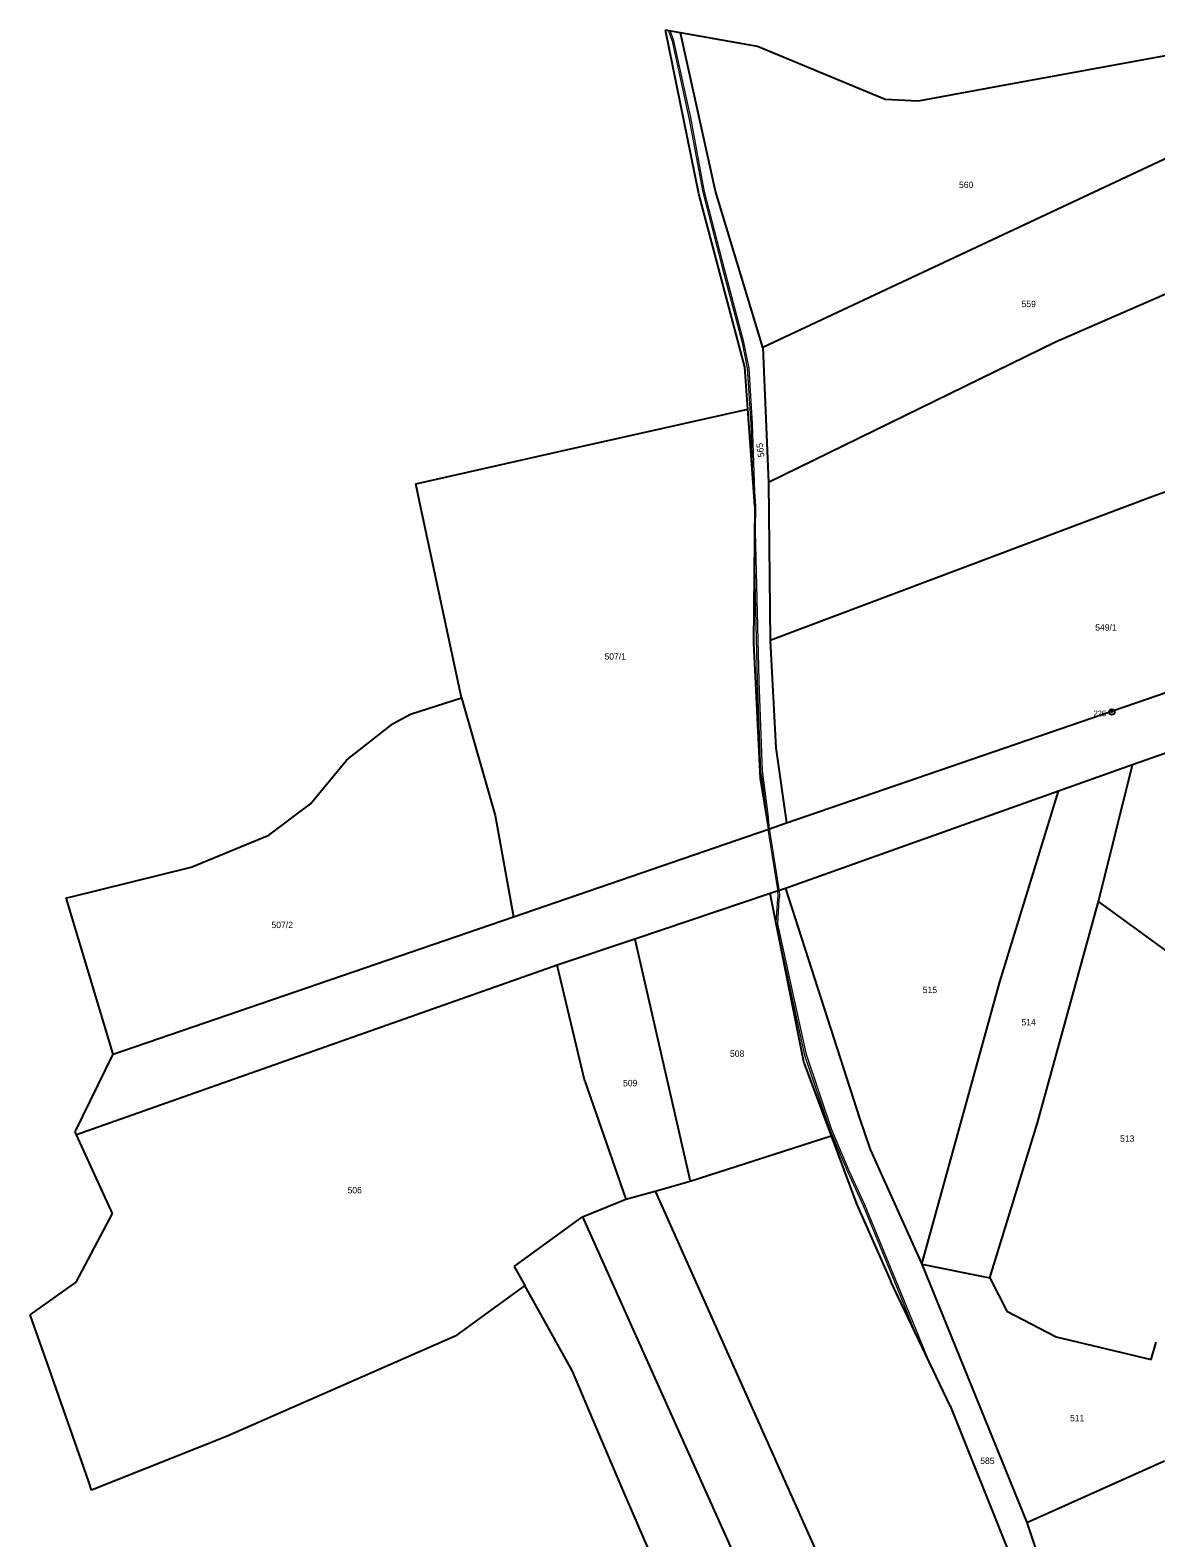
# Model space of a CAD drawing. Extents: x -664548 to -662415, y -1069720 to -1068208.
# Drawn here: x -664548.4 to -664249.9, y -1069341.5 to -1068942 of the extents above; entities that cross this region are included whole.
import ezdxf
from ezdxf.enums import TextEntityAlignment as Align

# ---------------------------------------------------------------- set-up
doc = ezdxf.new("R2010")
doc.units = 0
doc.header["$LTSCALE"] = 0.68
for name, color, linetype, lineweight in [('1', 7, 'Continuous', 25), ('13', 7, 'Continuous', 13), ('8', 7, 'Continuous', 25)]:
    doc.layers.add(name, color=color, linetype=linetype, lineweight=lineweight)
doc.layers.add('2', color=7, linetype='Continuous')

msp = doc.modelspace()

# ---------------------------------------------------------------- linework, layer by layer
at = {"layer": '1'}
for p, q in [((-664375.93, -1068942.69), (-664379.94, -1068941.98)), ((-664371.14, -1068985.33), (-664379.94, -1068941.98)), ((-664355.58, -1068946.3), (-664375.93, -1068942.69)), ((-664366.65, -1068984.69), (-664375.93, -1068942.69)), ((-664321.73, -1068960.32), (-664355.58, -1068946.3)), ((-664244.94, -1068948.35), (-664291.38, -1068956.85)), ((-664291.38, -1068956.85), (-664312.94, -1068960.8)), ((-664312.94, -1068960.8), (-664321.73, -1068960.32)), ((-664227.37, -1068966.62), (-664354.13, -1069026.11)), ((-664358.94, -1069031.29), (-664371.14, -1068985.33)), ((-664354.13, -1069026.11), (-664366.65, -1068984.69)), ((-664223.9, -1069001.69), (-664276.55, -1069024.67)), ((-664354.13, -1069026.11), (-664352.63, -1069061.84)), ((-664276.55, -1069024.67), (-664352.63, -1069061.84)), ((-664358.14, -1069042.38), (-664358.94, -1069031.29)), ((-664403.1, -1069052.48), (-664358.14, -1069042.38)), ((-664356.29, -1069068.06), (-664358.14, -1069042.38)), ((-664181.24, -1069041.54), (-664250, -1069065.31)), ((-664446.17, -1069062.16), (-664403.1, -1069052.48)), ((-664445.15, -1069066.92), (-664446.17, -1069062.16)), ((-664352.63, -1069061.84), (-664352.21, -1069103.72)), ((-664250, -1069065.31), (-664352.21, -1069103.72)), ((-664433.99, -1069118.89), (-664445.15, -1069066.92)), ((-664356.29, -1069068.06), (-664356.64, -1069104.38)), ((-664347.85, -1069152.04), (-664169.52, -1069090.79)), ((-664356.64, -1069104.38), (-664354.8, -1069140.28)), ((-664352.21, -1069103.72), (-664350.65, -1069132.16)), ((-664433.99, -1069118.89), (-664425.07, -1069150.06)), ((-664464.39, -1069135.33), (-664452.18, -1069125.7)), ((-664350.65, -1069132.16), (-664347.85, -1069152.04)), ((-664246.07, -1069133.11), (-664256.09, -1069136.68)), ((-664474.11, -1069147.02), (-664464.39, -1069135.33)), ((-664256.09, -1069136.68), (-664275.75, -1069143.67)), ((-664265.08, -1069172.85), (-664256.09, -1069136.68)), ((-664354.8, -1069140.28), (-664352.64, -1069153.69)), ((-664275.75, -1069143.67), (-664348.1, -1069169.43)), ((-664291.29, -1069194.2), (-664275.75, -1069143.67)), ((-664485.12, -1069155.29), (-664474.11, -1069147.02)), ((-664425.07, -1069150.06), (-664420.27, -1069176.92)), ((-664420.27, -1069176.92), (-664352.64, -1069153.69)), ((-664352.64, -1069153.69), (-664347.85, -1069152.04)), ((-664505.7, -1069163.78), (-664485.12, -1069155.29)), ((-664537.91, -1069171.7), (-664505.7, -1069163.78)), ((-664348.1, -1069169.43), (-664352.16, -1069170.79)), ((-664348.1, -1069169.43), (-664328.52, -1069230.33)), ((-664538.84, -1069171.93), (-664537.91, -1069171.7)), ((-664526.38, -1069213.36), (-664538.84, -1069171.93)), ((-664352.16, -1069170.79), (-664388.11, -1069182.84)), ((-664343.18, -1069215.8), (-664352.16, -1069170.79)), ((-664281.32, -1069231.52), (-664265.08, -1069172.85)), ((-664235.59, -1069194.44), (-664265.08, -1069172.85)), ((-664526.38, -1069213.36), (-664420.27, -1069176.92)), ((-664388.11, -1069182.84), (-664408.69, -1069189.74)), ((-664388.11, -1069182.84), (-664373.38, -1069247)), ((-664401.36, -1069220.5), (-664408.69, -1069189.74)), ((-664312, -1069269.03), (-664291.29, -1069194.2)), ((-664536.46, -1069233.88), (-664526.38, -1069213.36)), ((-664343.18, -1069215.8), (-664336.02, -1069234.94)), ((-664401.36, -1069220.5), (-664390.43, -1069251.77)), ((-664328.52, -1069230.33), (-664325.71, -1069238.59)), ((-664293.94, -1069272.63), (-664281.32, -1069231.52)), ((-664526.55, -1069255.58), (-664536.09, -1069234.68)), ((-664373.38, -1069247), (-664336.02, -1069234.94)), ((-664336.02, -1069234.94), (-664329.28, -1069252.98)), ((-664325.71, -1069238.59), (-664312, -1069269.03)), ((-664390.43, -1069251.77), (-664382.72, -1069249.61)), ((-664382.72, -1069249.61), (-664373.38, -1069247)), ((-664382.72, -1069249.61), (-664336.71, -1069352.37)), ((-664401.91, -1069256.47), (-664390.43, -1069251.77)), ((-664329.28, -1069252.98), (-664320.23, -1069273.57)), ((-664536.19, -1069273.74), (-664526.55, -1069255.58)), ((-664420.02, -1069269.62), (-664401.91, -1069256.47)), ((-664401.91, -1069256.47), (-664320.21, -1069438.74)), ((-664420.02, -1069269.62), (-664417.24, -1069274.6)), ((-664312, -1069269.03), (-664293.94, -1069272.63)), ((-664312, -1069269.03), (-664284.13, -1069337.46)), ((-664548.41, -1069282.37), (-664536.19, -1069273.74)), ((-664304.43, -1069306.57), (-664320.23, -1069273.57)), ((-664293.94, -1069272.63), (-664289.42, -1069281.44)), ((-664417.24, -1069274.6), (-664435.71, -1069288.06)), ((-664404.57, -1069297.31), (-664417.24, -1069274.6)), ((-664289.42, -1069281.44), (-664276.39, -1069288.21)), ((-664543.31, -1069296.93), (-664548.41, -1069282.37)), ((-664435.71, -1069288.06), (-664496.37, -1069314.67)), ((-664276.39, -1069288.21), (-664251.2, -1069294.26)), ((-664251.2, -1069294.26), (-664249.82, -1069289.64)), ((-664532.97, -1069326.4), (-664543.31, -1069296.93)), ((-664398.3, -1069312.16), (-664404.57, -1069297.31)), ((-664304.43, -1069306.57), (-664288.82, -1069345.56)), ((-664391.2, -1069328.98), (-664398.3, -1069312.16)), ((-664496.37, -1069314.67), (-664532.11, -1069328.85)), ((-664284.13, -1069337.46), (-664247.65, -1069321.07)), ((-664532.11, -1069328.85), (-664532.97, -1069326.4)), ((-664377.89, -1069359.38), (-664391.2, -1069328.98)), ((-664284.13, -1069337.46), (-664266.42, -1069390.2))]:
    msp.add_line(p, q, dxfattribs=at)
for points in [[(-664452.18, -1069125.7), (-664447.51, -1069123.28), (-664433.99, -1069118.89)], [(-664408.69, -1069189.74), (-664536.09, -1069234.68), (-664536.46, -1069233.88)]]:
    msp.add_lwpolyline(points, dxfattribs=at)
at = {"layer": '13'}
for points in [[(-664378.21, -1068944.93), (-664373.71, -1068965.22), (-664370.07, -1068984.93), (-664364.74, -1069005.48), (-664359.62, -1069024.79), (-664358.26, -1069031.57), (-664357.34, -1069046.2), (-664356.86, -1069060.18), (-664356.29, -1069068.06), (-664356.41, -1069080.64), (-664355.63, -1069114.39), (-664354.75, -1069138.24), (-664354.33, -1069141.01), (-664353.1, -1069150.83), (-664352.64, -1069153.69), (-664352.32, -1069153.58), (-664352.44, -1069152.81), (-664352.68, -1069149.8), (-664353.83, -1069140.95), (-664354.25, -1069138.2), (-664355.13, -1069114.37), (-664356.05, -1069074.65), (-664355.97, -1069068.06), (-664356.21, -1069064.45), (-664356.84, -1069046.18), (-664357.76, -1069031.51), (-664359.14, -1069024.67), (-664364.26, -1069005.36), (-664369.59, -1068984.83), (-664373.21, -1068965.12), (-664377.73, -1068944.79), (-664378.6, -1068942.22), (-664379.16, -1068942.12)], [(-664352.32, -1069153.58), (-664352.64, -1069153.69), (-664352.8, -1069153.74), (-664350.27, -1069169.71), (-664350.23, -1069170.14), (-664349.74, -1069169.98), (-664349.77, -1069169.65)], [(-664350.28, -1069172.25), (-664350.64, -1069178.39), (-664349.39, -1069184.66), (-664343.04, -1069213.57), (-664336.29, -1069233.58), (-664331.7, -1069244.47), (-664327.53, -1069253.43), (-664318.71, -1069274.9), (-664313.43, -1069287.78), (-664309.64, -1069295.7), (-664318.25, -1069274.72), (-664327.07, -1069253.23), (-664331.24, -1069244.27), (-664335.83, -1069233.4), (-664342.56, -1069213.43), (-664350.17, -1069178.8), (-664349.78, -1069172.31), (-664349.63, -1069171.41), (-664349.74, -1069169.98), (-664350.23, -1069170.14), (-664350.13, -1069171.39)]]:
    msp.add_lwpolyline(points, close=True, dxfattribs=at)
at = {"layer": '8'}
for radius in [0.75, 0.03]:
    msp.add_circle((-664261.6, -1069122.6798), radius, dxfattribs=at)

# ---------------------------------------------------------------- texts
at = {"layer": '2'}
for s, p in [('560', (-664302.12, -1068983.824)), ('559', (-664285.52, -1069015.385)), ('549/1', (-664266, -1069101.094)), ('507/1', (-664396.11, -1069108.785)), ('507/2', (-664484.41, -1069179.935)), ('515', (-664311.72, -1069197.155)), ('514', (-664285.55, -1069205.725)), ('508', (-664362.84, -1069214.045)), ('509', (-664391.2, -1069221.844)), ('513', (-664259.39, -1069236.545)), ('506', (-664464.24, -1069250.225)), ('511', (-664272.67, -1069310.615)), ('585', (-664296.47, -1069321.925))]:
    msp.add_text(s, height=1.7, dxfattribs=at).set_placement(p)
msp.add_text('565', height=1.7, rotation=98, dxfattribs=at).set_placement((-664353.689, -1069055.05))
at = {"layer": '8'}
msp.add_text('225', height=1.5, dxfattribs=at).set_placement((-664263.099, -1069123.797), align=Align.RIGHT)

doc.saveas('drawing.dxf')
